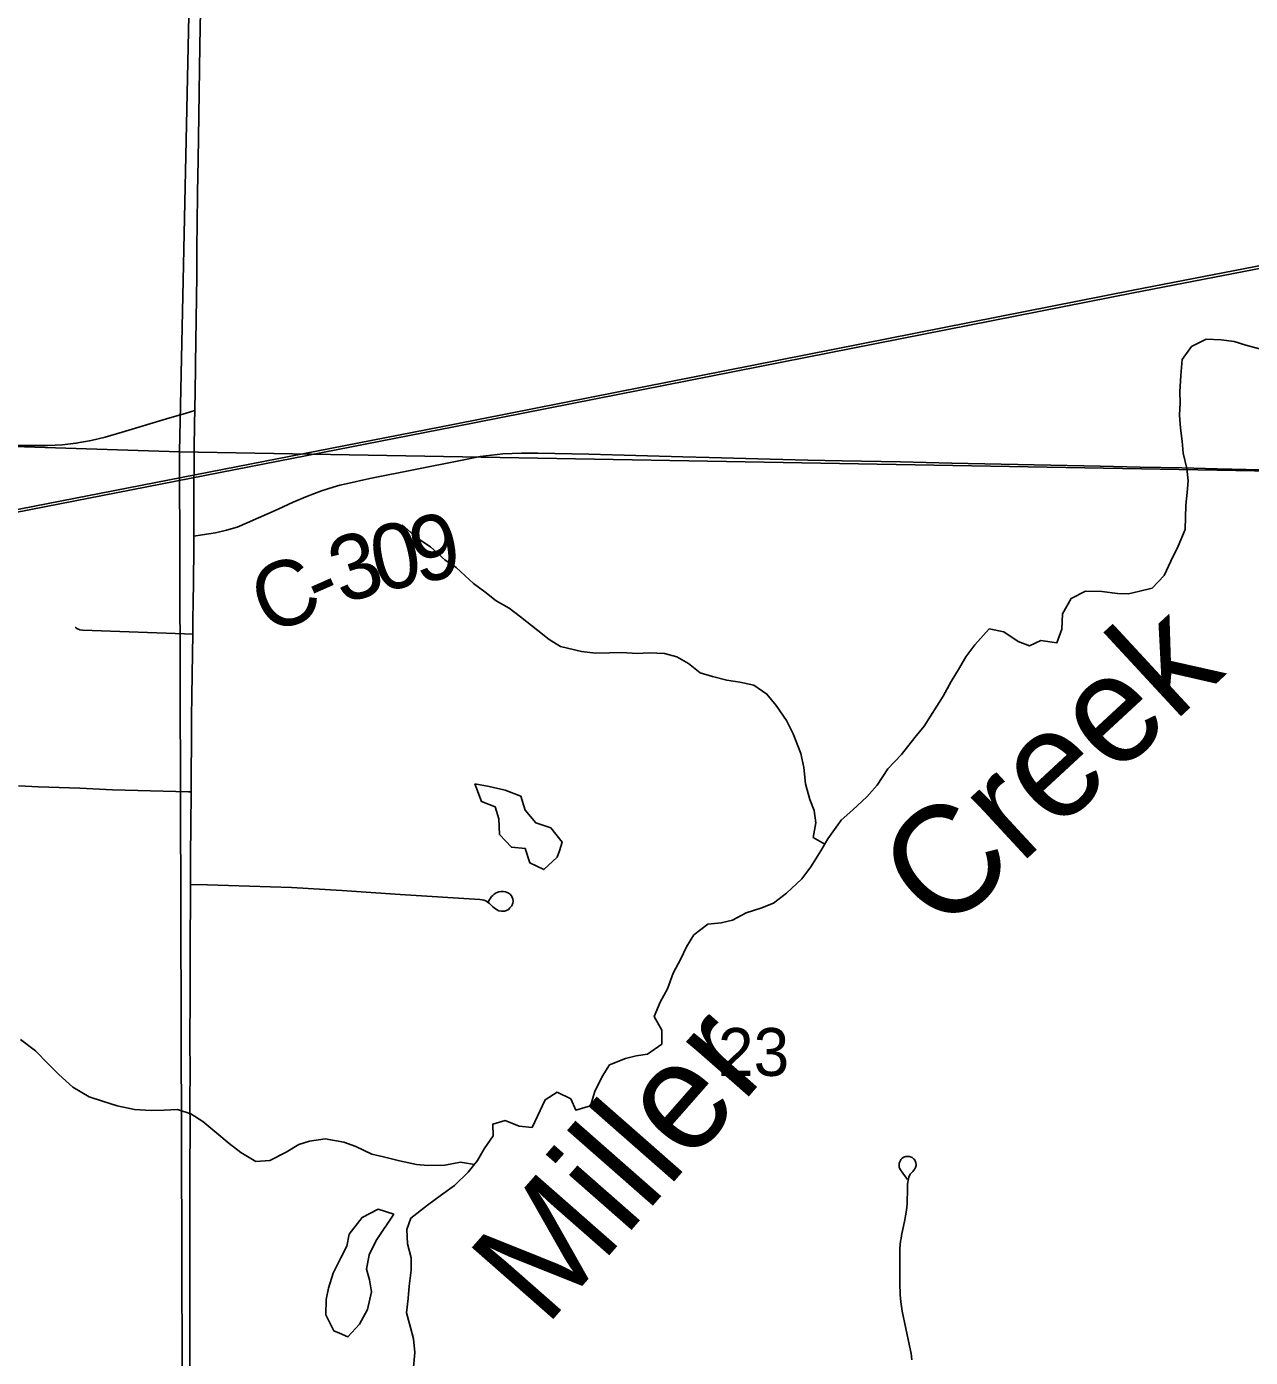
# Model space of a CAD drawing. Extents: x 0 to 34, y 0 to 22.
# Drawn here: x 3.588 to 4.658, y 16.807 to 17.97 of the extents above; entities that cross this region are included whole.
import ezdxf

# ---------------------------------------------------------------- set-up
doc = ezdxf.new("R2010")
doc.units = 0
for name, color, linetype in [('GM_X_Corporation', 7, 'Continuous'), ('GM_X_County_Road', 7, 'Continuous'), ('GM_X_County_Road_Text', 7, 'Continuous'), ('GM_X_Minor_Lake', 7, 'Continuous'), ('GM_X_Minor_River', 7, 'Continuous'), ('GM_X_Minor_River_Text', 7, 'Continuous'), ('GM_X_Rail_Line', 7, 'Continuous'), ('GM_X_Section_Text', 7, 'Continuous'), ('GM_X_State_Route', 7, 'Continuous'), ('GM_X_Township_Road', 7, 'Continuous')]:
    doc.layers.add(name, color=color, linetype=linetype)

msp = doc.modelspace()

# ---------------------------------------------------------------- linework, layer by layer
at = {"layer": 'GM_X_Corporation'}
for points in [[(2.7385, 18.6376), (3.7435, 18.6067), (3.7219, 17.5988), (2.7368, 17.6304)], [(3.7435, 18.6067), (4.7775, 18.5857), (4.7439, 17.5807), (3.7219, 17.5988)], [(2.7368, 17.6304), (3.7219, 17.5988), (3.7247, 16.5938), (2.7352, 16.6292)], [(3.7219, 17.5988), (4.7439, 17.5807), (4.7141, 16.575), (3.7247, 16.5938)]]:
    msp.add_lwpolyline(points, close=True, dxfattribs=at)
at = {"layer": 'GM_X_County_Road'}
for points in [[(3.5293, 17.6061), (3.5344, 17.6059), (3.5633, 17.6049), (3.5863, 17.6043), (3.6068, 17.6043), (3.6197, 17.605), (3.6314, 17.6063), (3.6448, 17.6087), (3.6568, 17.6116), (3.6717, 17.6159), (3.7106, 17.6275), (3.7277, 17.6327), (3.7352, 17.635)], [(3.7352, 17.635), (3.735, 17.6241), (3.7348, 17.6005), (3.7345, 17.5557), (3.7344, 17.5252)], [(3.7344, 17.5252), (3.7416, 17.5263), (3.7533, 17.5281), (3.7629, 17.5302), (3.7724, 17.5329), (3.7809, 17.5366), (3.8081, 17.5487), (3.8212, 17.5547), (3.8338, 17.5599), (3.846, 17.5646), (3.8561, 17.5678), (3.8619, 17.5695), (3.8676, 17.5709), (3.8883, 17.5754), (3.9675, 17.5913), (3.9846, 17.5946), (3.9945, 17.596), (4.0045, 17.5969), (4.0207, 17.5976), (4.035, 17.5977), (4.0797, 17.5966), (4.1617, 17.5944), (4.1847, 17.5938), (4.2381, 17.5924), (4.271, 17.5916), (4.3009, 17.591), (4.3519, 17.5899), (4.3969, 17.5889), (4.5266, 17.5863), (4.5614, 17.5855), (4.598, 17.5847), (4.6291, 17.584), (4.654, 17.5834), (4.7211, 17.5821)], [(3.7316, 17.2207), (3.7464, 17.2203), (3.8198, 17.2179), (3.8639, 17.2154), (3.9148, 17.212), (3.9843, 17.2075), (3.9864, 17.2073), (3.988, 17.2068), (3.9897, 17.2062), (3.9908, 17.2055), (3.9929, 17.2039), (3.9941, 17.2028), (3.9955, 17.2014), (3.9969, 17.2002), (3.9989, 17.1988), (4.0011, 17.1977), (4.0036, 17.1972), (4.006, 17.1973), (4.0078, 17.1979), (4.0094, 17.1988), (4.0107, 17.2001), (4.0122, 17.202), (4.0132, 17.2043), (4.0135, 17.2061), (4.0132, 17.2077), (4.0127, 17.2095), (4.0118, 17.2111), (4.0109, 17.2121), (4.01, 17.2128), (4.0084, 17.2137), (4.0067, 17.2142), (4.005, 17.2146), (4.003, 17.2145), (4.0009, 17.2142), (3.9987, 17.2134), (3.9969, 17.2122), (3.9956, 17.2111), (3.9946, 17.21), (3.9936, 17.2086), (3.9918, 17.2056)]]:
    msp.add_lwpolyline(points, dxfattribs=at)
at = {"layer": 'GM_X_Minor_Lake'}
for points in [[(3.9801, 17.3085), (3.9858, 17.2932), (3.9979, 17.2884), (4.0011, 17.2781), (4.0016, 17.2644), (4.012, 17.2532), (4.0241, 17.2522), (4.028, 17.2396), (4.0404, 17.2337), (4.052, 17.2445), (4.0539, 17.2501)], [(4.0539, 17.2501), (4.0564, 17.2577), (4.0464, 17.27), (4.0333, 17.2744), (4.024, 17.2856), (4.0201, 17.2978), (4.0065, 17.303), (3.9925, 17.3063), (3.9801, 17.3085)], [(3.9091, 16.9326), (3.8955, 16.9367), (3.8814, 16.9297), (3.8701, 16.9151), (3.868, 16.9046), (3.8629, 16.8944), (3.8562, 16.8809), (3.8521, 16.8677), (3.85, 16.8579), (3.8498, 16.8446), (3.8567, 16.8304), (3.8616, 16.8284)], [(3.8616, 16.8284), (3.8691, 16.8252), (3.8792, 16.8364), (3.8863, 16.8492), (3.8896, 16.8647), (3.8879, 16.875), (3.8854, 16.8845), (3.8876, 16.897), (3.8939, 16.9094), (3.9091, 16.9326)]]:
    msp.add_lwpolyline(points, dxfattribs=at)
at = {"layer": 'GM_X_Minor_River'}
for points in [[(4.6658, 17.6888), (4.6537, 17.6921), (4.6436, 17.6953), (4.6322, 17.6967), (4.6193, 17.6973), (4.6063, 17.6907), (4.5981, 17.6795), (4.5971, 17.6655), (4.5961, 17.6511), (4.5963, 17.6416), (4.596, 17.6309), (4.5966, 17.6195), (4.5983, 17.6081), (4.5992, 17.5975), (4.6024, 17.5841), (4.6033, 17.5735), (4.6027, 17.5633), (4.6014, 17.5523), (4.6009, 17.531), (4.5946, 17.5163), (4.5883, 17.5032), (4.5824, 17.4908), (4.5719, 17.4796), (4.5612, 17.4771), (4.5513, 17.4747), (4.5418, 17.4749), (4.5279, 17.4766), (4.5138, 17.4769), (4.5012, 17.4707), (4.4937, 17.4572), (4.4931, 17.4439), (4.4887, 17.4319), (4.4747, 17.434), (4.4647, 17.4293), (4.455, 17.4329), (4.4422, 17.4415), (4.4294, 17.444), (4.417, 17.4302), (4.4092, 17.4197), (4.4037, 17.41), (4.3963, 17.398), (4.3892, 17.3852), (4.3728, 17.359), (4.3646, 17.3492), (4.3529, 17.3343), (4.3409, 17.3216), (4.3316, 17.3074), (4.3227, 17.2973), (4.3103, 17.2858), (4.3003, 17.2769), (4.2886, 17.2604), (4.2823, 17.2499), (4.2737, 17.236), (4.2659, 17.2255), (4.2524, 17.2129), (4.2409, 17.2044), (4.2301, 17.2), (4.2172, 17.1957), (4.2053, 17.1895), (4.1954, 17.187), (4.1836, 17.1858), (4.1713, 17.1765), (4.165, 17.166), (4.1599, 17.1555), (4.1532, 17.1431), (4.1484, 17.1295), (4.1421, 17.1179), (4.1366, 17.1051), (4.1435, 17.0932), (4.1433, 17.081), (4.131, 17.0722), (4.1211, 17.0708), (4.1116, 17.0684), (4.0978, 17.0629), (4.0912, 17.0528), (4.0849, 17.0397), (4.0812, 17.0272), (4.0682, 17.0233), (4.0639, 17.0332), (4.0519, 17.0391)], [(4.2859, 17.2559), (4.2757, 17.2618), (4.2779, 17.2746), (4.2765, 17.2853), (4.2729, 17.2948), (4.269, 17.3086), (4.2674, 17.323), (4.265, 17.3352), (4.2581, 17.3524), (4.2523, 17.3639), (4.2434, 17.377), (4.2353, 17.387), (4.2237, 17.3949), (4.2116, 17.3974), (4.2002, 17.3991), (4.1878, 17.4024), (4.1769, 17.4056), (4.1668, 17.4138), (4.1566, 17.4197), (4.1457, 17.4225), (4.1324, 17.4232), (4.1218, 17.4226), (4.1086, 17.4233), (4.0976, 17.4231), (4.0854, 17.4229), (4.0733, 17.4243), (4.0548, 17.4285), (4.0451, 17.4347), (4.035, 17.4425), (4.02, 17.4546), (4.01, 17.462), (3.9987, 17.4686), (3.9886, 17.4764), (3.9789, 17.4838), (3.9636, 17.4978), (3.9539, 17.5044), (3.9412, 17.5157), (3.9292, 17.5235), (3.9166, 17.5351)], [(3.9797, 16.976), (3.9676, 16.9778), (3.9539, 16.9754), (3.9388, 16.9749), (3.9289, 16.9759), (3.9142, 16.9792), (3.9002, 16.9825), (3.89, 16.985), (3.8761, 16.9917), (3.8656, 16.9953), (3.8493, 16.9983), (3.8356, 16.9963), (3.8261, 16.9934), (3.815, 16.9868), (3.8008, 16.9795), (3.7887, 16.9786), (3.7755, 16.9864), (3.7654, 16.9942), (3.7528, 17.0047), (3.7423, 17.0136), (3.7318, 17.0203), (3.7201, 17.0239), (3.7084, 17.0234), (3.697, 17.0232), (3.6826, 17.0239), (3.6675, 17.0272), (3.6547, 17.0312), (3.643, 17.0349), (3.6287, 17.0435), (3.6164, 17.0544), (3.6068, 17.0641), (3.596, 17.0753), (3.5829, 17.085)], [(4.0519, 17.0391), (4.0415, 17.0325), (4.0348, 17.0182), (4.03, 17.0081), (4.0187, 17.0094), (4.0066, 17.0142), (3.9956, 17.011), (3.9961, 17.0008), (3.9883, 16.9895), (3.9824, 16.9794), (3.9743, 16.9693), (3.9623, 16.9574), (3.9508, 16.9493), (3.9385, 16.9404), (3.9242, 16.9289), (3.9206, 16.9191), (3.9211, 16.9066), (3.9243, 16.8944), (3.9245, 16.8834), (3.9227, 16.8694), (3.9217, 16.8587), (3.9203, 16.8462), (3.9239, 16.8333), (3.9263, 16.8234), (3.9276, 16.8116), (3.9263, 16.7987)]]:
    msp.add_lwpolyline(points, dxfattribs=at)
at = {"layer": 'GM_X_Rail_Line'}
for points in [[(2.1, 17.2578), (2.1839, 17.2743), (2.7373, 17.3807), (3.3215, 17.4979), (3.9612, 17.6228), (4.5554, 17.74), (5.1565, 17.8564), (5.7754, 17.979), (6.3342, 18.0908), (6.9022, 18.2018), (7.3492, 18.2882), (7.4239, 18.3027), (8.0092, 18.4168), (8.4623, 18.5082), (8.9, 18.5958)], [(2.1, 17.2555), (2.1844, 17.272), (2.7377, 17.3784), (3.3219, 17.4956), (3.9616, 17.6205), (4.5558, 17.7377), (5.157, 17.8541), (5.7759, 17.9767), (6.3346, 18.0885), (6.9026, 18.1995), (7.3496, 18.2859), (7.4243, 18.3004), (8.0097, 18.4146), (8.4624, 18.5056), (8.9, 18.5934)]]:
    msp.add_lwpolyline(points, dxfattribs=at)
at = {"layer": 'GM_X_State_Route'}
for points in [[(3.7374, 17.7975), (3.7377, 17.8255), (3.7382, 17.8541), (3.7388, 17.8926), (3.7397, 17.9535), (3.7412, 18.0306)], [(3.7359, 17.6757), (3.7369, 17.7528), (3.7371, 17.7782), (3.7374, 17.7975)], [(3.7352, 17.635), (3.7359, 17.6707), (3.7359, 17.6757)], [(3.7344, 17.5252), (3.7345, 17.5557), (3.7348, 17.6005), (3.735, 17.6241), (3.7352, 17.635)], [(3.7336, 17.4554), (3.7337, 17.4643), (3.7343, 17.5116), (3.7344, 17.5252)], [(3.7324, 17.3672), (3.7332, 17.4221), (3.7334, 17.4395), (3.7336, 17.4554)], [(3.7309, 16.7967), (3.7309, 16.8315), (3.7308, 16.8881), (3.7308, 16.9129), (3.7308, 16.9515), (3.7308, 16.9745), (3.7311, 17.0049), (3.731, 17.0329), (3.7311, 17.0559), (3.731, 17.0851), (3.7312, 17.1217), (3.7311, 17.1591), (3.7316, 17.2207), (3.7316, 17.2401), (3.7315, 17.2462), (3.7319, 17.2716), (3.732, 17.3017), (3.7323, 17.3612), (3.7324, 17.3672)]]:
    msp.add_lwpolyline(points, dxfattribs=at)
at = {"layer": 'GM_X_Township_Road'}
for points in [[(3.6308, 17.4456), (3.6322, 17.4445), (3.6347, 17.4433), (3.6374, 17.4428), (3.6457, 17.4425), (3.7264, 17.4397), (3.7334, 17.4395)], [(3.5813, 17.3068), (3.5987, 17.3061), (3.6347, 17.3047), (3.6632, 17.3034), (3.7299, 17.3017), (3.732, 17.3017)], [(4.362, 16.8052), (4.3613, 16.8107), (4.36, 16.8173), (4.3566, 16.8325), (4.3536, 16.8478), (4.3524, 16.8558), (4.3518, 16.8621), (4.3513, 16.8721), (4.3513, 16.8839), (4.3513, 16.8976), (4.3515, 16.9026), (4.3521, 16.9089), (4.3525, 16.9113), (4.3528, 16.9138), (4.3557, 16.9276), (4.3563, 16.931), (4.357, 16.9343), (4.3575, 16.9384), (4.3578, 16.9419), (4.3579, 16.9465), (4.358, 16.9505), (4.3582, 16.9581), (4.3585, 16.9608), (4.3589, 16.9632), (4.3593, 16.9647), (4.3596, 16.9657), (4.3602, 16.9667), (4.3606, 16.9674), (4.3628, 16.9699), (4.3646, 16.9722), (4.3651, 16.9733), (4.3654, 16.9742), (4.3656, 16.9749), (4.3656, 16.9758), (4.3654, 16.9774), (4.3649, 16.979), (4.3645, 16.9797), (4.364, 16.9804), (4.3635, 16.9809), (4.3628, 16.9815), (4.3622, 16.982), (4.3614, 16.9824), (4.3599, 16.9829), (4.3592, 16.983), (4.3582, 16.983), (4.3566, 16.9828), (4.3557, 16.9825), (4.355, 16.9822), (4.3536, 16.9814), (4.3529, 16.9808), (4.3524, 16.9802), (4.352, 16.9795), (4.3516, 16.9788), (4.3511, 16.9776), (4.3509, 16.9767), (4.3508, 16.975), (4.351, 16.9734), (4.3519, 16.9713), (4.354, 16.9683), (4.3582, 16.9629)]]:
    msp.add_lwpolyline(points, dxfattribs=at)

# ---------------------------------------------------------------- texts
at = {"layer": 'GM_X_County_Road_Text'}
for s, rotation, p in [('9', 12.1405, (3.9301, 17.4832)), ('3', 17.9384, (3.8641, 17.4653)), ('0', 12.2443, (3.8959, 17.4757)), ('C', 22.0283, (3.7991, 17.4383)), ('-', 23.7453, (3.8441, 17.4565))]:
    msp.add_text(s, height=0.0568, rotation=rotation, dxfattribs=at).set_placement(p)
at = {"layer": 'GM_X_Minor_River_Text'}
for s, rotation, p in [('Creek', 42.7839, (4.3893, 17.1753)), ('Miller', 48.7053, (4.0417, 16.833))]:
    msp.add_text(s, height=0.09477, rotation=rotation, dxfattribs=at).set_placement(p)
at = {"layer": 'GM_X_Section_Text'}
msp.add_text('23', height=0.04186, rotation=0, dxfattribs=at).set_placement((4.1925, 17.0533))

doc.saveas('drawing.dxf')
